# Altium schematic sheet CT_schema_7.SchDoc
size 278 x 170 mm
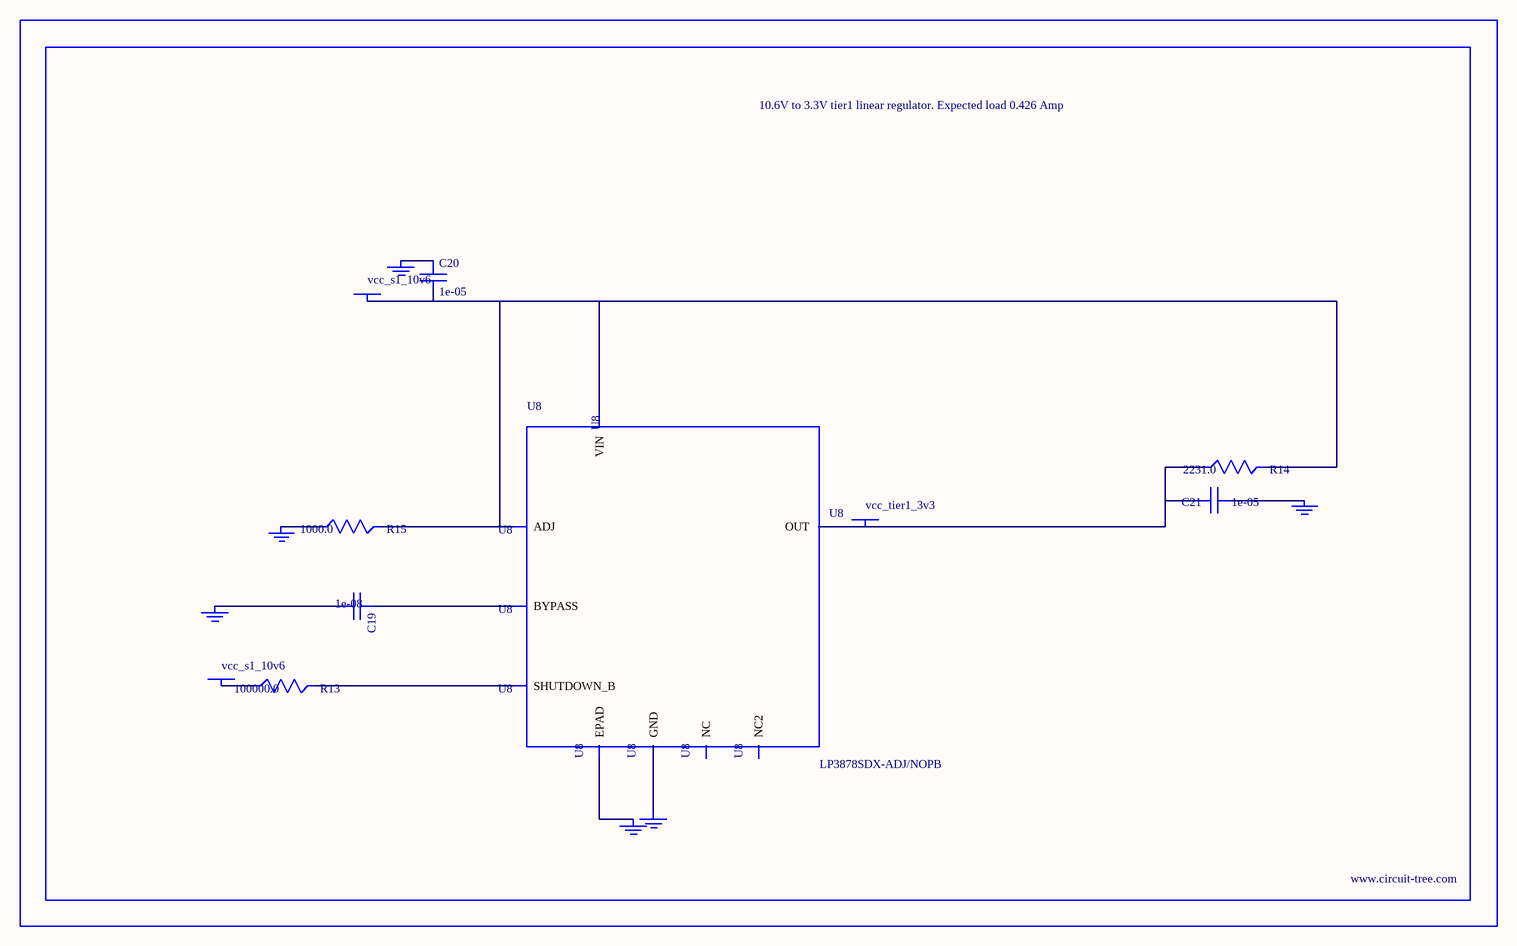
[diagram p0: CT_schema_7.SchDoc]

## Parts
BORDER6  (no value)
C19  1e-08  [C0402]
C20  1e-05  [C1206]
C21  1e-05  [C1210]
GND_INSTANCE_6_0  (no value)
GND_INSTANCE_6_1  (no value)
GND_INSTANCE_6_2  (no value)
GND_INSTANCE_6_3  (no value)
GND_INSTANCE_6_4  (no value)
GND_INSTANCE_6_5  (no value)
POWER_INSTANCE_6_0  vcc_s1_10v6
POWER_INSTANCE_6_1  vcc_s1_10v6
POWER_INSTANCE_6_2  vcc_tier1_3v3
R13  100000.0  [R0603]
R14  2231.0  [R0603]
R15  1000.0  [R0603]
U8  LP3878SDX-ADJ/NOPB  [WSON-8]

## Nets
NetC19_1: C19.1 U8.1(BYPASS)
NetC19_2: C19.2 GND_INSTANCE_6_0.0(GND)
NetC20_1: C20.1 GND_INSTANCE_6_1.0(GND)
NetC20_2: C20.2 POWER_INSTANCE_6_0.0(PWR) R14.2 R15.2 U8.4(VIN) U8.6(ADJ)
NetC21_1: C21.1 GND_INSTANCE_6_2.0(GND)
NetC21_2: C21.2 POWER_INSTANCE_6_2.0(PWR) R14.1 U8.5(OUT)
NetGND_INSTANCE_6_3_0: GND_INSTANCE_6_3.0(GND) R15.1
NetGND_INSTANCE_6_4_0: GND_INSTANCE_6_4.0(GND) U8.PAD(EPAD)
NetGND_INSTANCE_6_5_0: GND_INSTANCE_6_5.0(GND) U8.3(GND)
NetPOWER_INSTANCE_6_1_0: POWER_INSTANCE_6_1.0(PWR) R13.1
NetR13_2: R13.2 U8.8(SHUTDOWN_B)

Not connected (* = marked no-connect by the designer): U8 2(NC) 7(NC2)

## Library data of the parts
BORDER6 = BORDER_PAGE6
C19 = C0402C103K3RAC
C20 = C1206C106K3RACTU
C21 = GRM32DR61E106MA12L
GND_INSTANCE_6_0-GND_INSTANCE_6_5 = GND
POWER_INSTANCE_6_0-POWER_INSTANCE_6_2 = PWR
R13 = RC0603JR-07100KL
R14 = R14
R15 = RC0603JR-071KL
